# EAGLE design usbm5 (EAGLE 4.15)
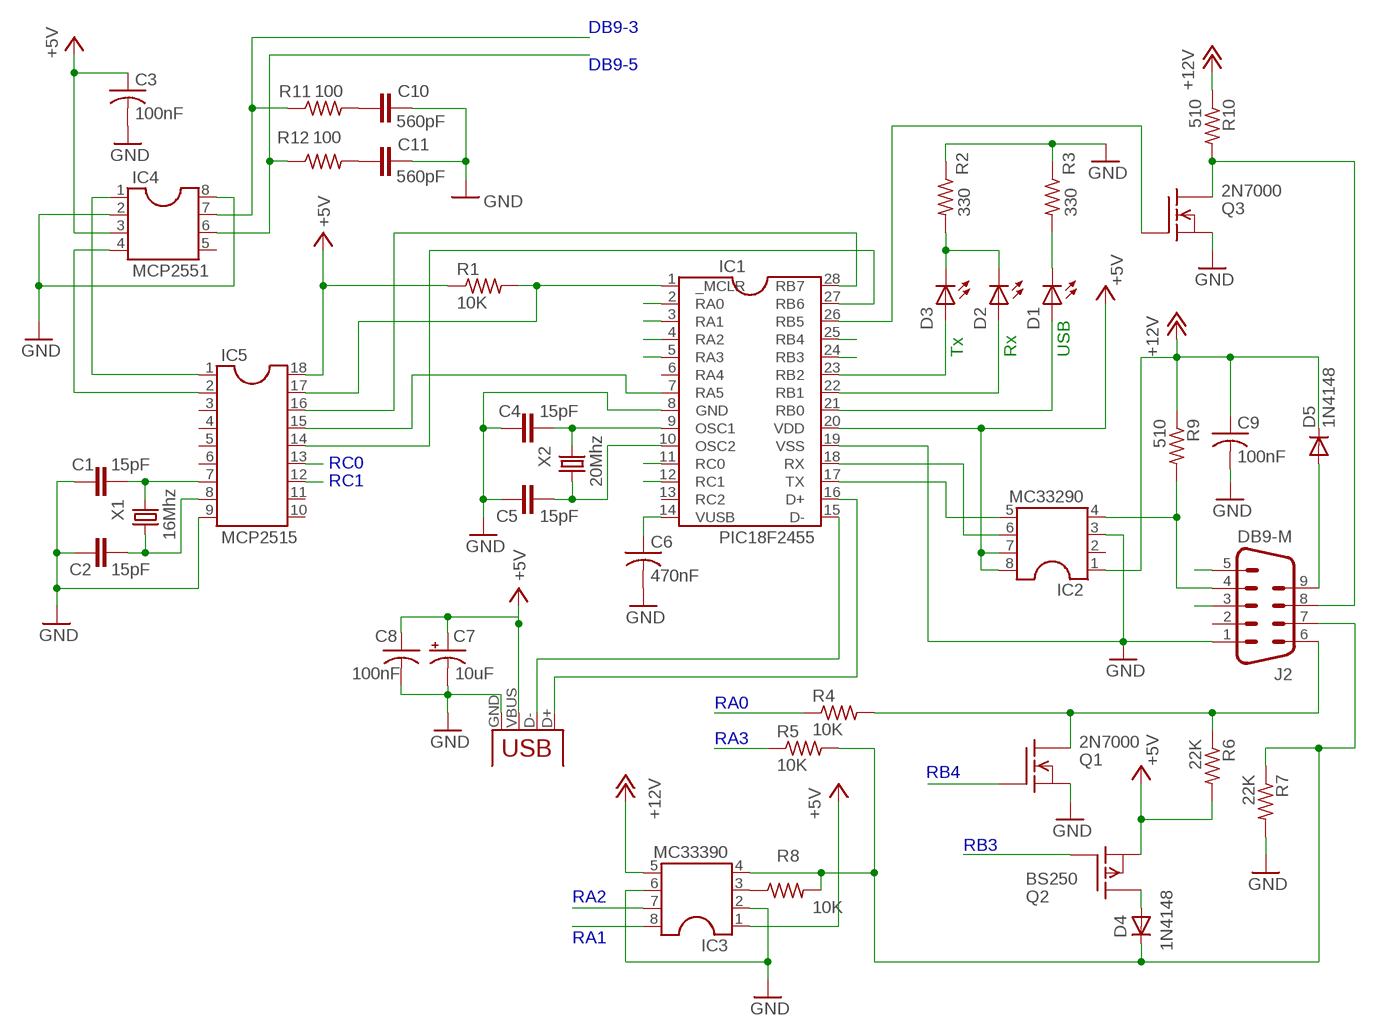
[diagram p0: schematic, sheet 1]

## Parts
C1  15pF  C2.5/2  [C2.5-2]
C2  15pF  C2.5/2  [C2.5-2]
C3  100nF  C-US050-025X075  [C050-025X075]
C4  15pF  C2.5/2  [C2.5-2]
C5  15pF  C2.5/2  [C2.5-2]
C6  470nF  C-US050-050X075  [C050-050X075]
C7  10uF  CPOL-USE2-4  [E2-4]
C8  100nF  C-US050-025X075  [C050-025X075]
C9  100nF  C-US050-025X075  [C050-025X075]
C10  560pF  C2.5/2  [C2.5-2]
C11  560pF  C2.5/2  [C2.5-2]
D1  LED5MM  [LED5MM]
D2  LED5MM  [LED5MM]
D3  LED5MM  [LED5MM]
D4  1N4148  1N4148M  [D035-10M]
D5  1N4148  1N4148M  [D035-10M]
IC1  PIC18F2455  [DIL28]
IC2  MC33290  SO-8  [SO-8]
IC3  MC33390  SO-8  [SO-8]
IC4  MCP2551  DIL8  [DIL08]
IC5  MCP2515  DIL18  [DIL18]
J1  USB-B-H  [USB-B-H]
J2  DB9-M  M09HP  [M09HP]
Q1  2N7000  TN0602N3  [TO-92]
Q2  BS250  BSS110  [TO92]
Q3  2N7000  TN0602N3  [TO-92]
R1  10K  R-US_0207/10  [0207/10]
R2  330  R-US_0207/10  [0207/10]
R3  330  R-US_0207/10  [0207/10]
R4  10K  R-US_0207/10  [0207/10]
R5  10K  R-US_0207/10  [0207/10]
R6  22K  R-US_0207/10  [0207/10]
R7  22K  R-US_0207/10  [0207/10]
R8  10K  R-US_0207/10  [0207/10]
R9  510  R-US_0207/10  [0207/10]
R10  510  R-US_0207/10  [0207/10]
R11  100  R-US_0207/10  [0207/10]
R12  100  R-US_0207/10  [0207/10]
X1  16Mhz  CRYTALHC49S  [HC49/S]
X2  20Mhz  CRYTALHC49S  [HC49/S]

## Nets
+5V: C3.1 C7.+ C8.1 IC1.20(VDD) IC2.7 IC2.8 IC3.1 IC4.3 IC5.18 J1.VBUS Q2.1(S) R1.1 R6.2
+12V: C9.1 D5.C IC2.1 IC3.5 R9.1 R10.1
GND: C1.1 C2.2 C3.2 C4.1 C5.2 C6.2 C7.- C8.2 C9.2 C10.1 C11.1 IC1.8(GND) IC1.19(VSS) IC2.3 IC3.2 IC3.6 IC4.2 IC4.8 IC5.9 J1.GND J2.1 Q1.1(S) Q3.1(S) R2.1 R3.1 R7.2
N$1: IC1.17(TX) IC2.5
N$2: J2.8 Q3.3(D) R10.2
N$3: D3.A IC1.23(RB2)
N$4: D2.A IC1.22(RB1)
N$5: D1.A IC1.21(RB0)
N$6: IC1.3(RA1) IC3.8
N$7: D5.A J2.9
N$8: D2.K(C) D3.K(C) R2.2
N$9: IC1.5(RA3) R5.1
N$10: D1.K(C) R3.2
N$11: IC1.15(D-) J1.D-
N$12: IC1.16(D+) J1.D+
N$13: IC1.2(RA0) R4.1
N$14: IC1.26(RB5) Q3.2(G)
N$15: IC1.27(RB6) IC5.14
N$16: IC1.28(RB7) IC5.16
N$17: IC1.1(_MCLR) IC5.17 R1.2
N$18: D4.C IC3.4 J2.7 R5.2 R7.1 R8.2
N$19: IC4.1 IC5.1
N$20: IC4.4 IC5.2
N$21: C4.2 IC1.9(OSC1) X2.2
N$22: C6.1 IC1.14(VUSB)
N$23: IC1.18(RX) IC2.6
N$24: IC1.24(RB3) Q2.2(G)
N$25: D4.A Q2.3(D)
N$26: IC1.25(RB4) Q1.2(G)
N$27: J2.6 Q1.3(D) R4.2 R6.1
N$29: IC2.4 J2.4 R9.2
N$30: IC1.11(RC0) IC5.13
N$32: IC1.4(RA2) IC3.7
N$33: IC3.3 R8.1
N$34: C5.1 IC1.10(OSC2) X2.1
N$35: C11.2 R12.2
N$36: C10.2 R11.2
N$37: IC1.7(RA5) IC5.15
N$38: IC4.7 J2.3 R11.1
N$39: IC4.6 J2.5 R12.1
N$40: C1.2 IC5.7 X1.2
N$41: C2.1 IC5.8 X1.1
SCK: IC1.12(RC1) IC5.12
Unconnected: IC1.6(RA4) IC1.13(RC2) IC2.2 IC4.5 IC5.3 IC5.4 IC5.5 IC5.6 IC5.10 IC5.11 J2.2

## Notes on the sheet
- DB9-3
- DB9-5
- Tx | Rx | USB
- RC0
- RC1
- RA0
- RA3
- RB4
- RB3
- RA2
- RA1

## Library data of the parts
C1 C2 C4 C5 C10 C11 = capacitor-wima:C: CAPACITOR
C3 C6 C8 C9 = rcl:C-US: CAPACITOR, American symbol
C7 = rcl:CPOL-US: POLARIZED CAPACITOR, American symbol
D1-D3 = led:LED: LED
D4 D5 = diode:1N4148: DIODE
IC1 = pic18f2455:PIC18F2455
IC2 IC3 = so-8:SO-8
IC4 = ic-package:DIL8: Dual In Line
IC5 = ic-package:DIL18: Dual In Line
J1 = con-usb:USB: USB Connectors
J2 = con-subd:M09: SUB-D
Q1 Q3 = transistor-fet:TN0602N3: N-Channel Enhancement MOSFET 20V; 4A; 0,75Ohm
Q2 = transistor-fet:BSS110: P-Channel Enhancement MOSFET -50V; -0,17A; 6Ohm
R1-R12 = rcl:R-US_: RESISTOR, American symbol
X1 X2 = crystal:CRYTAL: CRYSTAL

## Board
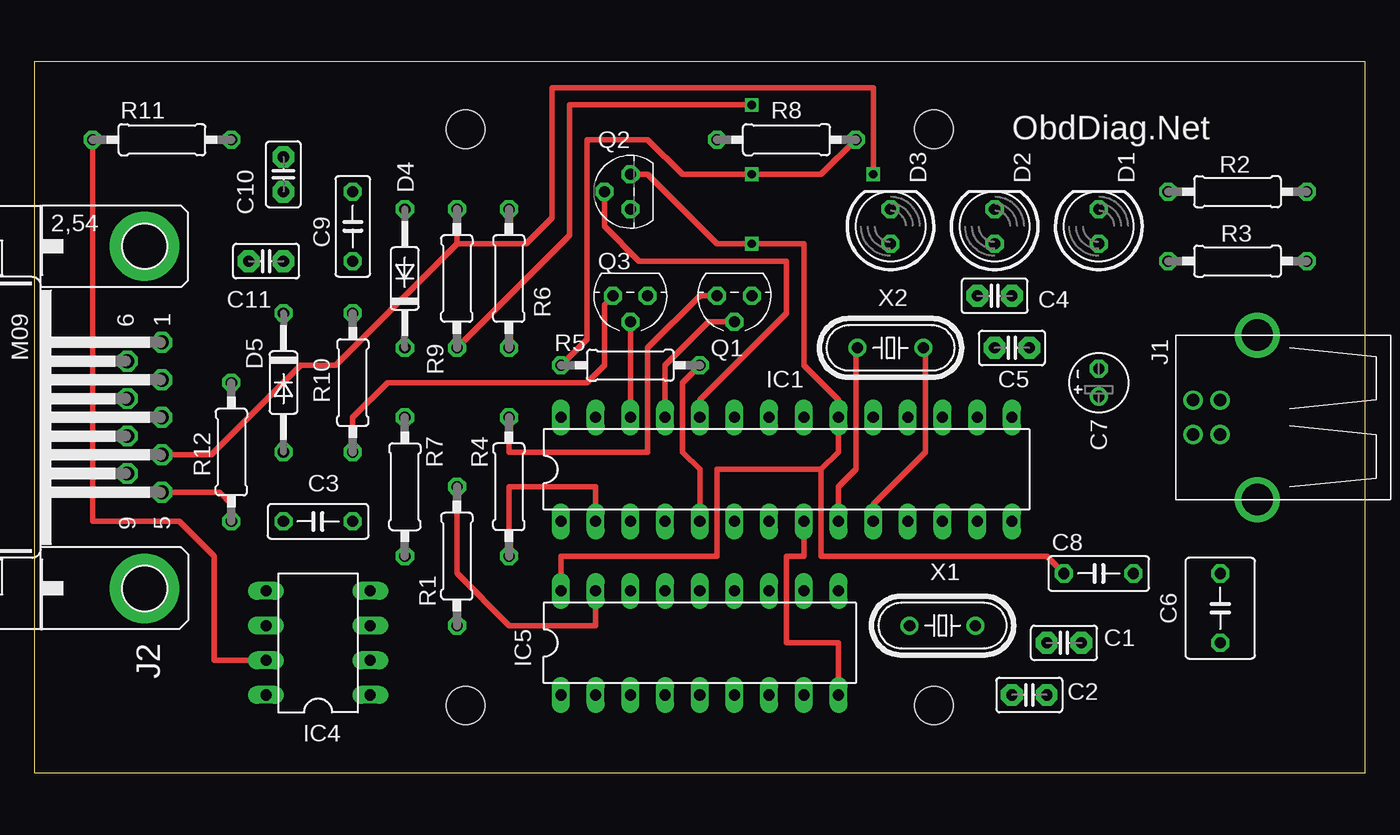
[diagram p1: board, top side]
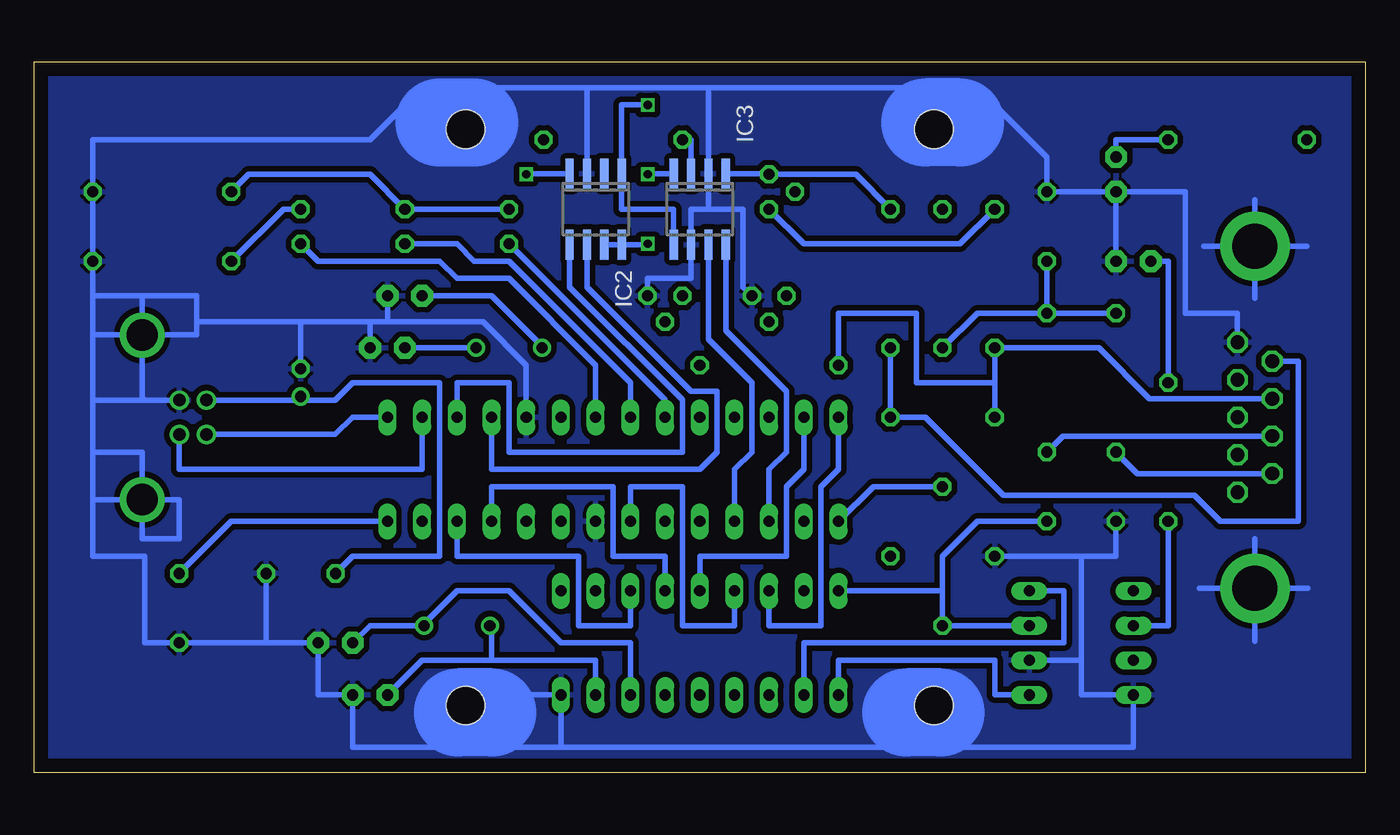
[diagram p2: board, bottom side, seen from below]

Size 97.46 x 52.06 mm. Coordinates in mm from the lower left corner, seen from the top.
Outline: 0,0 97.46,0 97.46,52.06 0,52.06 0,0
Copper layers (1*16): Top 0.035mm / dielectric 1.5mm / Bottom 0.035mm
Design rules "default": minimum track width 10mil, minimum drill 24mil, track to track 8mil, track to pad 8mil, pad to pad 8mil, via to via 8mil, smd to smd 8mil, copper to edge 40mil, drill to drill 8mil, minimum pad ring 10mil, minimum via ring 8mil, stop-mask expansion 4mil, vias tented up to drill 0mil, thermal gap 10mil
Holes 2.8 mm at 31.58,47.11 65.88,47.11 31.58,4.95 65.88,4.95

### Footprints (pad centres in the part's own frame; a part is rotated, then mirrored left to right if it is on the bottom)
C2.5-2 = drill 0.813 pad 1.6 octagon: 1 -1.27,0; 2 1.27,0
C050-025X075 = drill 0.813 octagon: 1 -2.54,0; 2 2.54,0
C050-050X075 = drill 0.813 octagon: 1 -2.54,0; 2 2.54,0
E2-4 = drill 0.813 pad 1.27 round: + -1.016,0 | drill 0.813 pad 1.27 octagon: - 1.016,0
LED5MM = drill 0.813 octagon: A -1.27,0; K 1.27,0
D035-10M = drill 0.813 octagon: A 5.08,0; C -5.08,0
DIL28 = drill 0.813 long: 1 -16.51,-3.81; 2 -13.97,-3.81; 3 -11.43,-3.81; 4 -8.89,-3.81; 5 -6.35,-3.81; 6 -3.81,-3.81; 7 -1.27,-3.81; 8 1.27,-3.81; 9 3.81,-3.81; 10 6.35,-3.81; 11 8.89,-3.81; 12 11.43,-3.81; 13 13.97,-3.81; 14 16.51,-3.81; 15 16.51,3.81; 16 13.97,3.81; 17 11.43,3.81; 18 8.89,3.81; 19 6.35,3.81; 20 3.81,3.81; 21 1.27,3.81; 22 -1.27,3.81; 23 -3.81,3.81; 24 -6.35,3.81; 25 -8.89,3.81; 26 -11.43,3.81; 27 -13.97,3.81; 28 -16.51,3.81
SO-8 = smd 0.6 x 2.2: 1 -1.905,-2.6; 2 -0.635,-2.6; 3 0.635,-2.6; 4 1.905,-2.6; 5 1.905,2.6; 6 0.635,2.6; 7 -0.635,2.6; 8 -1.905,2.6
DIL08 = drill 0.813 long: 1 -3.81,-3.81; 2 -1.27,-3.81; 3 1.27,-3.81; 4 3.81,-3.81; 5 3.81,3.81; 6 1.27,3.81; 7 -1.27,3.81; 8 -3.81,3.81
DIL18 = drill 0.813 long: 1 -10.16,-3.81; 2 -7.62,-3.81; 3 -5.08,-3.81; 4 -2.54,-3.81; 5 0,-3.81; 6 2.54,-3.81; 7 5.08,-3.81; 8 7.62,-3.81; 9 10.16,-3.81; 10 10.16,3.81; 11 7.62,3.81; 12 5.08,3.81; 13 2.54,3.81; 14 0,3.81; 15 -2.54,3.81; 16 -5.08,3.81; 17 -7.62,3.81; 18 -10.16,3.81
USB-B-H = drill 0.914 round: D+ 0,1.25; D- 1.981,1.25; GND 0,-1.25; VBUS 1.981,-1.25 | drill 2.286 round: P$1 -2.718,-6.02; P$2 -2.718,6.02
M09HP = drill 1.016 octagon: 1 -5.486,1.27; 2 -2.743,1.27; 3 0,1.27; 4 2.743,1.27; 5 5.486,1.27; 6 -4.115,-1.27; 7 -1.372,-1.27; 8 1.372,-1.27; 9 4.115,-1.27 | drill 3.302 pad 5.08 round: G1 -12.522,0; G2 12.522,0
TO-92 = drill 0.813 octagon: 1 -1.27,0; 2 0,1.905; 3 1.27,0
TO92 = drill 0.813 octagon: 1 1.27,0; 2 0,1.905; 3 -1.27,0
0207/10 = drill 0.813 octagon: 1 -5.08,0; 2 5.08,0
HC49/S = drill 0.813 round: 1 -2.413,0; 2 2.413,0

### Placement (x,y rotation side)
C1  75.4,9.52 180 top
C2  72.86,5.71 0 top
C3  20.79,18.41 180 top
C4  70.32,34.92 180 top
C5  71.59,31.11 0 top
C6  86.83,12.06 270 top
C7  77.94,28.57 90 top
C8  77.94,14.6 0 top
C9  23.33,40 90 top
C10  18.25,43.81 90 top
C11  16.98,37.46 180 top
D1  77.94,40 90 top
D2  70.32,40 90 top
D3  62.7,40 90 top
D4  27.14,36.19 90 top
D5  18.25,28.57 270 top
IC1  55.08,22.22 0 top
IC2  56.35,41.27 180 bottom
IC3  48.73,41.27 180 bottom
IC4  20.79,9.52 90 top
IC5  48.73,9.52 0 top
J1  86.83,26.03 180 top
J2  8.09,26.03 270 top
Q1  51.27,34.92 180 top
Q2  43.65,42.54 90 top
Q3  43.65,34.92 180 top
R1  30.95,15.87 90 top
R2  88.1,42.54 180 top
R3  88.1,37.46 180 top
R4  34.76,20.95 90 top
R5  43.65,29.84 180 top
R6  34.76,36.19 90 top
R7  27.14,20.95 270 top
R8  55.08,46.35 0 top
R9  30.95,36.19 90 top
R10  23.33,28.57 270 top
R11  9.36,46.35 0 top
R12  14.44,23.49 90 top
X1  66.51,10.79 0 top
X2  62.7,31.11 180 top

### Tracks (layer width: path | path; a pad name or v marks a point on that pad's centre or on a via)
+5V  (via drill 0.6)
  Top 0.406: Q2.1 44.92,43.81 50,38.73 v52.54,38.73 56.35,38.73 56.35,29.84 58.89,27.3 IC1.20 58.89,23.49 57.62,22.22 | 57.62,22.22 50,22.22 50,15.87 38.57,15.87 IC5.18 | 57.62,22.22 57.62,15.87 74.13,15.87 C8.1
  Bottom 0.406: 55.66,38.67 55.71,38.73 IC2.7 IC2.8 | IC2.8 52.54,38.67 v52.54,38.73 | IC2.8 54.45,38.73 | R6.2 37.3,43.81 Q2.1 43.71,43.87 IC3.1 | IC3.1 46.82,43.81 | IC3.1 46.82,44.45 | IC4.3 R1.1 30.95,13.33 | 77.94,27.28 75.42,27.28 74.13,28.57 67.78,28.57 67.78,15.87 74.13,15.87 C8.1 | 77.94,27.28 J1.VBUS | 77.94,27.28 C7.+ | C3.1 28.41,18.41 30.95,15.87 30.95,13.33 | 30.95,13.33 IC5.18
+12V  (via drill 0.6)
  Top 0.406: R9.1 39.2,39.37 39.2,48.89 v52.54,48.89
  Bottom 0.406: IC3.5 50.63,41.27 54.45,41.27 IC2.1 54.45,48.89 v52.54,48.89 | R10.1 28.41,33.65 R9.1 | R10.1 C9.1 | D5.C R10.1
GND
  Top 0.406: IC5.9 58.89,9.52 55.08,9.52 55.08,15.87 56.35,15.87 IC1.8
  Bottom 0.406: J2.1 9.36,33.65 13.17,33.65 13.17,42.54 C10.1 | Q1.1 52.54,36.19 49.37,36.19 IC3.6 49.37,41.27 48.09,41.27 | Q3.1 45.55,35.55 45.55,41.27 48.09,41.27 | IC1.19 61.43,29.84 64.61,33.02 71.59,33.02 | 48.09,41.27 IC3.2 48.09,50.16 | 58.89,1.9 74.13,1.9 C2.2 76.67,5.71 C1.1 80.48,9.52 | 20.79,8.25 IC4.2 | 20.79,8.25 20.79,15.87 | 20.79,15.87 18.25,15.87 C3.2 | 69.05,50.16 56.98,50.16 | 56.98,50.16 48.09,50.16 | 56.98,50.16 IC2.3 | J1.GND 89.37,27.28 89.37,27.3 89.56,27.28 | 69.05,50.16 72.86,46.35 93.18,46.35 R2.1 R3.1 93.18,36.19 | 48.09,50.16 28.41,50.16 | 58.89,1.9 IC5.9 62.7,5.71 62.7,4.44 63.91,4.44 | 80.48,9.52 C6.2 89.37,9.52 89.37,15.87 93.18,15.87 93.18,19.68 | 31.58,1.9 58.89,1.9 | 20.79,8.25 20.79,5.71 IC4.8 16.98,1.9 30.95,1.9 | 20.79,15.87 R7.2 | C10.1 C9.2 23.33,45.08 28.41,50.16 | C10.1 C11.1 | 80.48,9.52 C8.2 | 71.59,33.02 C4.1 | 77.94,33.02 85.56,33.02 85.56,33.65 | 77.94,33.02 C7.- | 93.18,36.19 93.18,35.55 | 93.18,19.68 93.18,20.95 | 93.18,27.28 93.18,32.06 | 93.18,32.06 93.18,34.92 | 93.18,34.92 93.18,36.19 | 85.56,33.65 85.56,34.92 89.56,34.92 | 93.18,34.92 89.56,34.92 | 93.18,27.28 89.56,27.28 | 72.86,33.02 71.59,33.02 | 77.94,33.02 72.86,33.02 | 72.86,33.02 C5.2 | 10,38.54 11.84,38.54 | 8.09,40.7 8.09,41.97 | 4.28,38.54 6.06,38.54 | 8.09,34.73 8.09,36.25 | 10.06,13.52 12.15,13.52 | 8.09,15.62 8.09,17.14 | 8.09,9.65 8.09,11.55 | 4.22,13.52 6.18,13.52 | 89.56,34.92 89.56,33.46 | 93.18,32.06 90.89,32.06 | 92.16,20 91.85,20 | 93.18,19.68 93.18,20 | 92.16,20 90.89,20 | 31.58,1.9 32.22,1.9 | 28.41,50.16 29.68,50.16 29.68,47.62 | 69.05,50.16 67.78,50.16 67.78,47.62 | 30.95,1.9 31.58,1.9 | 30.95,1.9 32.22,1.9 | 31.08,4.44 32.22,4.44 32.22,1.9
  Bottom 0.406: 88.16,32.06 85.56,32.06 85.56,33.65 | 89.56,27.28 89.56,30.47 | 89.56,21.39 89.56,23.49 93.18,23.49 | 93.18,20 92.16,20 | 93.18,20.95 93.18,20 | 93.18,20.95 93.18,23.49 | 93.18,23.49 93.18,27.28 | 88.16,20 86.83,20 86.83,17.14 89.56,17.14 89.56,18.54
  Bottom 6.452: 29.68,47.62 32.22,47.62 | 67.78,47.62 65.24,47.62 | 63.91,4.44 66.45,4.44 | 31.08,4.44 33.62,4.44
  pour Bottom (isolate 0.406): 0.47,51.43 96.99,51.43 96.99,50.16 96.99,0.63 0.47,0.63 0.47,1.9
N$1
  Bottom 0.406: IC1.17 66.51,28.57 62.7,28.57 62.7,23.49 50,23.49 50,27.3 58.25,35.55 IC2.5 58.25,38.73
N$2
  Top 0.406: R10.2 23.33,26.03 25.87,28.57 40.48,28.57 41.74,29.84 41.74,34.29 Q3.3
  Bottom 0.406: J2.8 22.16,24.66 R10.2
N$3
  Bottom 0.406: IC1.23 51.27,27.3 D3.A
N$4
  Bottom 0.406: IC1.22 53.81,28.57 62.7,37.46 65.24,37.46 66.51,38.73 D2.A
N$5
  Bottom 0.406: IC1.21 56.35,29.84 62.7,36.19 66.51,36.19 67.78,37.46 76.67,37.46 D1.A
N$6
  Bottom 0.406: IC1.3 43.65,22.22 42.38,23.49 42.38,27.93 46.82,32.38 IC3.8 46.82,38.73
N$7
  Bottom 0.406: J2.9 16.67,21.91 D5.A
N$8
  Bottom 0.406: D3.K D2.K 72.86,43.81 81.75,43.81 R2.2
N$9
  Top 0.406: IC1.5 48.73,22.22 47.46,23.49 47.46,28.57 R5.1
N$10
  Bottom 0.406: D1.K 79.21,41.27 R3.2
N$11
  Bottom 0.406: 71.59,26.05 71.61,26.05 IC1.15 74.13,26.03 75.42,24.78 J1.D-
N$12
  Bottom 0.406: IC1.16 69.05,22.22 86.83,22.22 J1.D+
N$13
  Top 0.406: R4.1 34.76,20.95 41.11,20.95 IC1.2
N$14
  Top 0.406: IC1.26 Q3.2
N$15
  Bottom 0.406: IC1.27 41.11,22.22 42.38,20.95 42.38,15.87 48.73,15.87 IC5.14
N$16
  Bottom 0.406: IC1.28 38.57,22.22 39.84,20.95 39.84,10.79 43.65,10.79 IC5.16
N$17
  Top 0.406: 36.03,10.79 35.39,10.79 | 36.03,10.79 41.11,10.79 IC5.17 | R1.2 30.95,14.6 34.76,10.79 36.03,10.79
  Bottom 0.406: IC1.1 36.03,20.95 R1.2
N$18  (via drill 0.6)
  Top 0.406: R5.2 40.48,31.74 40.48,46.35 44.92,46.35 47.46,43.81 v52.54,43.81 57.62,43.81 R8.2
  Bottom 0.406: IC3.4 52.48,43.87 v52.54,43.81 | R5.2 38.57,33.65 32.85,33.65 32.85,28.57 27.14,28.57 | J2.7 15.81,27.4 19.52,31.11 D4.C 27.14,28.57 | 27.14,28.57 R7.1
N$19
  Bottom 0.406: IC4.1 27.14,5.71 27.14,8.25 38.57,8.25 IC5.1
N$20
  Bottom 0.406: IC4.4 22.06,13.33 22.06,9.52 41.11,9.52 IC5.2
N$21
  Top 0.406: IC1.9 58.89,20.95 60.16,22.22 60.16,31.11 X2.2
  Bottom 0.406: C4.2 63.97,34.92 60.16,31.11 X2.2
N$22
  Bottom 0.406: IC1.14 83.02,18.41 C6.1
N$23
  Bottom 0.406: IC1.18 63.97,22.22 48.73,22.22 47.46,23.49 47.46,27.93 49.37,27.93 56.98,35.55 IC2.6 56.98,38.73
N$24
  Top 0.406: Q2.2 41.74,40 44.28,37.46 55.08,37.46 55.08,33.65 48.73,27.3 IC1.24
N$25
  Bottom 0.406: D4.A 29.68,38.73 41.11,38.73 Q2.3
N$26
  Top 0.406: IC1.25 46.19,29.84 49.37,33.02 Q1.2
N$27
  Top 0.406: R4.2 34.76,23.49 44.92,23.49 44.92,31.11 48.73,34.92 Q1.3
  Bottom 0.406: J2.6 4.92,30.14 4.92,18.41 10.63,18.41 12.54,20.31 26.5,20.31 32.22,26.03 R4.2 R6.1
N$29  (via drill 0.6)
  Top 0.406: v61.43,43.81 61.43,50.16 37.94,50.16 37.94,40.64 36.03,38.73 30.95,38.73 | J2.4 12.97,23.29 19.52,29.84 22.06,29.84 30.95,38.73 | 30.95,38.73 R9.2
  Bottom 0.406: IC2.4 61.37,43.87 v61.43,43.81
N$30
  Bottom 0.406: IC5.13 51.27,15.87 55.08,15.87 55.08,20.95 63.97,20.95 IC1.11
N$31
  Bottom 0.406: 67.78,28.57 74.13,28.57
N$32
  Bottom 0.406: IC1.4 46.19,22.22 44.92,23.49 44.92,28.57 48.09,31.74 IC3.7 48.09,38.73
N$33
  Bottom 0.406: IC3.3 49.37,46.35 R8.1
N$34
  Top 0.406: IC1.10 61.43,19.68 65.24,23.49 65.24,31.11 X2.1
  Bottom 0.406: X2.1 C5.1
N$35
  Bottom 0.406: R12.2 14.44,37.46 C11.2
N$36
  Bottom 0.406: R11.2 18.25,46.35 C10.2
N$37
  Bottom 0.406: IC5.15 46.19,10.79 50,10.79 50,20.95 53.81,20.95 IC1.7
N$38
  Top 0.406: 5.55,26.03 4.92,26.03 | 5.55,26.03 J2.3 | 5.55,18.41 10.63,18.41 13.17,15.87 13.17,8.25 IC4.7 | 5.55,18.41 4.92,18.41 | 4.28,26.03 4.28,18.41 5.55,18.41 | 4.28,26.03 R11.1 | 4.28,26.03 5.55,26.03
N$39
  Top 0.406: J2.5 13.58,20.54 14.44,19.68 R12.1
  Bottom 0.406: R12.1 14.44,10.79 IC4.6
N$40
  Bottom 0.406: IC5.7 53.81,9.52 58.89,9.52 62.7,13.33 66.51,13.33 69.05,10.79 | C1.2 72.86,10.79 69.05,10.79 | 69.05,10.79 X1.2
N$41
  Bottom 0.406: 64.1,10.66 X1.1 63.97,10.79 63.97,8.25 | IC5.8 56.35,8.25 63.97,8.25 | C2.1 69.05,8.25 63.97,8.25
SCK
  Bottom 0.406: IC5.12 53.81,10.79 57.62,10.79 57.62,15.87 66.51,15.87 IC1.12

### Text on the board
tNames: ObdDiag.Net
